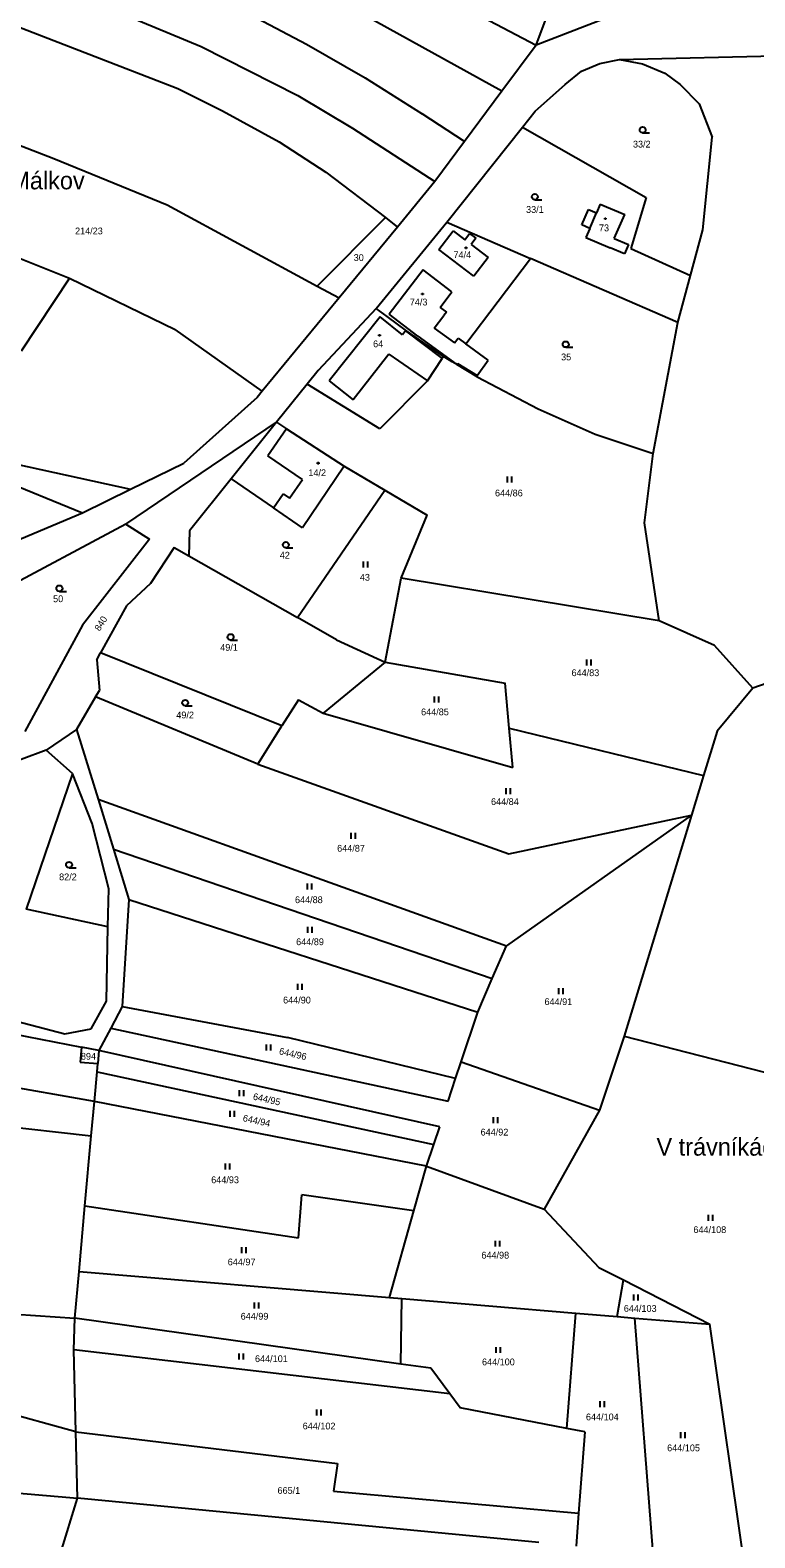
# Model space of a CAD drawing. Extents: x -791032 to -787751, y -1106872 to -1104403.
# Drawn here: x -789370.7 to -789189, y -1105599.2 to -1105221.6 of the extents above; entities that cross this region are included whole.
import ezdxf

# ---------------------------------------------------------------- set-up
doc = ezdxf.new("R2010")
doc.units = 0
for name, color, linetype in [('Vrstva 1', 7, 'Continuous'), ('Vrstva 14', 7, 'Continuous'), ('Vrstva 15', 7, 'Continuous'), ('Vrstva 2', 7, 'Continuous'), ('Vrstva 23', 7, 'Continuous'), ('Vrstva 25', 7, 'Continuous'), ('Vrstva 36', 7, 'Continuous'), ('Vrstva 39', 7, 'Continuous')]:
    doc.layers.add(name, color=color, linetype=linetype)

msp = doc.modelspace()

# ---------------------------------------------------------------- linework, layer by layer
at = {"layer": 'Vrstva 1'}
for p, q in [((-789285.39, -1105203.5), (-789243.84, -1105225.4)), ((-789370.26, -1105208.04), (-789327.75, -1105225.68)), ((-789252.41, -1105236.92), (-789298.86, -1105211.23)), ((-789243.84, -1105225.4), (-789238.63, -1105211.34)), ((-789386.31, -1105215.88), (-789333.63, -1105236.24)), ((-789313.74, -1105218.64), (-789301.43, -1105225.11)), ((-789226.96, -1105218.88), (-789243.84, -1105225.4)), ((-789301.43, -1105225.11), (-789286.69, -1105233.54)), ((-789327.75, -1105225.68), (-789303.58, -1105237.99)), ((-789243.84, -1105225.4), (-789252.41, -1105236.92)), ((-789227.84, -1105229.97), (-789222.94, -1105228.96)), ((-789222.94, -1105228.96), (-789175.36, -1105227.85)), ((-789222.94, -1105228.96), (-789217.17, -1105230.01)), ((-789236.59, -1105235.22), (-789232.43, -1105231.85)), ((-789232.43, -1105231.85), (-789227.84, -1105229.97)), ((-789217.17, -1105230.01), (-789211.57, -1105232.35)), ((-789211.57, -1105232.35), (-789207.7, -1105235.2)), ((-789333.63, -1105236.24), (-789322.44, -1105241.84)), ((-789286.69, -1105233.54), (-789272.38, -1105242.59)), ((-789240.29, -1105238.55), (-789236.59, -1105235.22)), ((-789207.7, -1105235.2), (-789202.93, -1105240.1)), ((-789303.58, -1105237.99), (-789289.9, -1105246.16)), ((-789252.41, -1105236.92), (-789261.75, -1105249.48)), ((-789244.09, -1105241.93), (-789240.29, -1105238.55)), ((-789202.93, -1105240.1), (-789199.71, -1105248.4)), ((-789322.44, -1105241.84), (-789308.28, -1105249.58)), ((-789261.75, -1105249.48), (-789272.38, -1105242.59)), ((-789247.25, -1105245.91), (-789244.09, -1105241.93)), ((-789388.44, -1105244.65), (-789364.69, -1105253.72)), ((-789289.9, -1105246.16), (-789269.22, -1105259.52)), ((-789266.18, -1105269.7), (-789247.25, -1105245.91)), ((-789247.25, -1105245.91), (-789216.22, -1105263.55)), ((-789308.28, -1105249.58), (-789296.51, -1105257.14)), ((-789261.75, -1105249.48), (-789269.22, -1105259.52)), ((-789202.09, -1105271.58), (-789199.71, -1105248.4)), ((-789364.69, -1105253.72), (-789336.29, -1105265.34)), ((-789296.51, -1105257.14), (-789281.6, -1105268.55)), ((-789269.22, -1105259.52), (-789278.59, -1105270.91)), ((-789336.29, -1105265.34), (-789298.72, -1105285.7)), ((-789232.37, -1105270.39), (-789230.72, -1105266.53)), ((-789230.72, -1105266.53), (-789228.7, -1105267.39)), ((-789227.75, -1105265.19), (-789228.7, -1105267.39)), ((-789227.75, -1105265.19), (-789221.64, -1105267.79)), ((-789216.22, -1105263.55), (-789220.12, -1105276.28)), ((-789298.72, -1105285.7), (-789281.6, -1105268.55)), ((-789283.9, -1105291.34), (-789266.18, -1105269.7)), ((-789281.6, -1105268.55), (-789278.59, -1105270.91)), ((-789266.18, -1105269.7), (-789245.27, -1105278.79)), ((-789230.35, -1105271.25), (-789232.37, -1105270.39)), ((-789224.26, -1105273.8), (-789221.64, -1105267.79)), ((-789278.59, -1105270.91), (-789293.22, -1105288.68)), ((-789268.2, -1105276.58), (-789264.6, -1105271.89)), ((-789264.6, -1105271.89), (-789261.74, -1105274.1)), ((-789261.74, -1105274.1), (-789260.51, -1105272.51)), ((-789260.51, -1105272.51), (-789258.92, -1105273.69)), ((-789258.92, -1105273.69), (-789260.15, -1105275.29)), ((-789230.35, -1105271.25), (-789231.34, -1105273.55)), ((-789231.34, -1105273.55), (-789225.26, -1105276.09)), ((-789224.26, -1105273.8), (-789220.7, -1105275.29)), ((-789205.18, -1105283.05), (-789202.09, -1105271.58)), ((-789382.55, -1105275), (-789360.79, -1105283.75)), ((-789259.48, -1105283.24), (-789268.2, -1105276.58)), ((-789260.15, -1105275.29), (-789255.88, -1105278.56)), ((-789221.66, -1105277.59), (-789225.26, -1105276.09)), ((-789220.7, -1105275.29), (-789221.66, -1105277.59)), ((-789220.12, -1105276.28), (-789205.18, -1105283.05)), ((-789261.47, -1105300.17), (-789245.27, -1105278.79)), ((-789255.88, -1105278.56), (-789259.48, -1105283.24)), ((-789208.35, -1105294.83), (-789245.27, -1105278.79)), ((-789360.79, -1105283.75), (-789372.88, -1105302)), ((-789360.79, -1105283.75), (-789334.28, -1105296.6)), ((-789298.72, -1105285.7), (-789293.22, -1105288.68)), ((-789208.35, -1105294.83), (-789205.18, -1105283.05)), ((-789293.22, -1105288.68), (-789312.46, -1105312.05)), ((-789283.9, -1105291.34), (-789298.48, -1105306.86)), ((-789281.14, -1105293.36), (-789283.9, -1105291.34)), ((-789312.46, -1105312.05), (-789334.28, -1105296.6)), ((-789276.3, -1105296.9), (-789281.14, -1105293.36)), ((-789267.05, -1105303.34), (-789276.3, -1105296.9)), ((-789214.52, -1105327.65), (-789208.35, -1105294.83)), ((-789255.84, -1105304.27), (-789261.47, -1105300.17)), ((-789271.03, -1105309.45), (-789267.36, -1105303.81)), ((-789267.05, -1105303.34), (-789267.36, -1105303.81)), ((-789264.87, -1105304.65), (-789267.05, -1105303.34)), ((-789258.6, -1105308.11), (-789255.84, -1105304.27)), ((-789298.48, -1105306.86), (-789301.19, -1105310.24)), ((-789263.73, -1105305.34), (-789264.87, -1105304.65)), ((-789263.58, -1105305.1), (-789263.73, -1105305.34)), ((-789258.63, -1105308.41), (-789263.73, -1105305.34)), ((-789263.58, -1105305.1), (-789258.6, -1105308.11)), ((-789312.46, -1105312.05), (-789313.76, -1105313.63)), ((-789301.19, -1105310.24), (-789308.87, -1105319.81)), ((-789283.02, -1105321.43), (-789301.19, -1105310.24)), ((-789271.03, -1105309.45), (-789283.02, -1105321.43)), ((-789258.63, -1105308.41), (-789243.3, -1105316.44)), ((-789313.76, -1105313.63), (-789332.15, -1105330.05)), ((-789243.3, -1105316.44), (-789229.02, -1105322.78)), ((-789346.71, -1105345.3), (-789308.87, -1105319.81)), ((-789308.87, -1105319.81), (-789320.23, -1105333.97)), ((-789308.87, -1105319.81), (-789306.41, -1105321.42)), ((-789306.41, -1105321.42), (-789291.98, -1105330.84)), ((-789229.02, -1105322.78), (-789214.52, -1105327.65)), ((-789395.29, -1105327.04), (-789357.53, -1105342.45)), ((-789377.52, -1105329.52), (-789345.54, -1105336.59)), ((-789345.54, -1105336.59), (-789332.15, -1105330.05)), ((-789291.98, -1105330.84), (-789302.36, -1105346.26)), ((-789291.98, -1105330.84), (-789281.77, -1105336.81)), ((-789216.65, -1105344.97), (-789214.52, -1105327.65)), ((-789320.23, -1105333.97), (-789330.68, -1105346.99)), ((-789320.23, -1105333.97), (-789309.63, -1105341.26)), ((-789357.53, -1105342.45), (-789345.54, -1105336.59)), ((-789303.67, -1105368.7), (-789281.77, -1105336.81)), ((-789281.77, -1105336.81), (-789271.14, -1105343.03)), ((-789302.36, -1105346.26), (-789309.63, -1105341.26)), ((-789409.67, -1105364.4), (-789357.53, -1105342.45)), ((-789346.71, -1105345.3), (-789381.96, -1105364.16)), ((-789346.71, -1105345.3), (-789340.72, -1105349.12)), ((-789277.68, -1105358.85), (-789271.14, -1105343.03)), ((-789213.03, -1105369.56), (-789216.65, -1105344.97)), ((-789340.72, -1105349.12), (-789357.5, -1105370.6)), ((-789330.68, -1105346.99), (-789330.92, -1105353.22)), ((-789334.57, -1105351.15), (-789340.51, -1105360.15)), ((-789334.57, -1105351.15), (-789330.92, -1105353.22)), ((-789330.92, -1105353.22), (-789303.67, -1105368.7)), ((-789340.51, -1105360.15), (-789346.51, -1105365.76)), ((-789281.67, -1105379.86), (-789277.68, -1105358.85)), ((-789213.03, -1105369.56), (-789277.68, -1105358.85)), ((-789346.51, -1105365.76), (-789352.99, -1105377.52)), ((-789293.88, -1105374.26), (-789303.67, -1105368.7)), ((-789357.5, -1105370.6), (-789371.98, -1105397.25)), ((-789199.13, -1105375.67), (-789213.03, -1105369.56)), ((-789293.88, -1105374.26), (-789281.67, -1105379.86)), ((-789189.55, -1105386.43), (-789199.13, -1105375.67)), ((-789353.96, -1105379.28), (-789352.99, -1105377.52)), ((-789353.96, -1105379.28), (-789353.31, -1105386.97)), ((-789307.55, -1105395.84), (-789352.99, -1105377.52)), ((-789281.67, -1105379.86), (-789297.25, -1105392.63)), ((-789281.67, -1105379.86), (-789251.59, -1105385.16)), ((-789177.3, -1105382.12), (-789189.55, -1105386.43)), ((-789354.27, -1105388.6), (-789353.31, -1105386.97)), ((-789250.58, -1105396.4), (-789251.59, -1105385.16)), ((-789189.55, -1105386.43), (-789198.49, -1105397.16)), ((-789354.27, -1105388.6), (-789359, -1105396.72)), ((-789313.59, -1105405.39), (-789354.27, -1105388.6)), ((-789303.42, -1105389.34), (-789307.55, -1105395.84)), ((-789303.42, -1105389.34), (-789297.25, -1105392.63)), ((-789297.25, -1105392.63), (-789249.7, -1105406.22)), ((-789359, -1105396.72), (-789366.67, -1105401.92)), ((-789359, -1105396.72), (-789353.64, -1105414.19)), ((-789313.59, -1105405.39), (-789307.55, -1105395.84)), ((-789250.58, -1105396.4), (-789201.88, -1105408.26)), ((-789249.7, -1105406.22), (-789250.58, -1105396.4)), ((-789198.49, -1105397.16), (-789201.88, -1105408.26)), ((-789366.67, -1105401.92), (-789394.2, -1105412.1)), ((-789360.03, -1105407.78), (-789366.67, -1105401.92)), ((-789313.59, -1105405.39), (-789250.65, -1105427.9)), ((-789360.03, -1105407.78), (-789371.65, -1105441.77)), ((-789355.07, -1105420.31), (-789360.03, -1105407.78)), ((-789201.88, -1105408.26), (-789204.91, -1105418.19)), ((-789353.64, -1105414.19), (-789349.8, -1105426.7)), ((-789353.64, -1105414.19), (-789251.26, -1105450.9)), ((-789350.96, -1105436.62), (-789355.07, -1105420.31)), ((-789204.91, -1105418.19), (-789251.26, -1105450.9)), ((-789250.65, -1105427.9), (-789204.91, -1105418.19)), ((-789204.91, -1105418.19), (-789221.79, -1105473.54)), ((-789349.8, -1105426.7), (-789345.92, -1105439.33)), ((-789349.8, -1105426.7), (-789254.83, -1105459.12)), ((-789351.15, -1105446.16), (-789350.96, -1105436.62)), ((-789345.92, -1105439.33), (-789347.58, -1105466.12)), ((-789345.92, -1105439.33), (-789258.47, -1105467.51)), ((-789351.15, -1105446.16), (-789371.65, -1105441.77)), ((-789351.53, -1105464.8), (-789351.15, -1105446.16)), ((-789254.83, -1105459.12), (-789251.26, -1105450.9)), ((-789258.47, -1105467.51), (-789254.83, -1105459.12)), ((-789411.01, -1105460.08), (-789361.97, -1105472.94)), ((-789355.35, -1105471.72), (-789351.53, -1105464.8)), ((-789347.58, -1105466.12), (-789350.45, -1105471.55)), ((-789347.58, -1105466.12), (-789306.15, -1105473.87)), ((-789262.61, -1105479.95), (-789258.47, -1105467.51)), ((-789378.46, -1105472.29), (-789357.82, -1105476.28)), ((-789361.97, -1105472.94), (-789355.35, -1105471.72)), ((-789350.45, -1105471.55), (-789353.41, -1105477.13)), ((-789350.45, -1105471.55), (-789265.9, -1105489.85)), ((-789264.01, -1105484.16), (-789306.15, -1105473.87)), ((-789221.79, -1105473.54), (-789227.97, -1105492.04)), ((-789221.79, -1105473.54), (-789163.41, -1105488.56)), ((-789357.82, -1105476.28), (-789358.13, -1105480.02)), ((-789353.41, -1105477.13), (-789357.82, -1105476.28)), ((-789353.41, -1105477.13), (-789353.7, -1105480.42)), ((-789268.01, -1105496.22), (-789353.41, -1105477.13)), ((-789354.56, -1105489.92), (-789416.33, -1105479.05)), ((-789358.13, -1105480.02), (-789353.7, -1105480.42)), ((-789353.88, -1105482.44), (-789353.7, -1105480.42)), ((-789264.01, -1105484.16), (-789262.61, -1105479.95)), ((-789262.61, -1105479.95), (-789227.97, -1105492.04)), ((-789354.56, -1105489.92), (-789353.88, -1105482.44)), ((-789353.88, -1105482.44), (-789269.48, -1105500.65)), ((-789265.9, -1105489.85), (-789264.01, -1105484.16)), ((-789405.54, -1105492.93), (-789355.33, -1105498.49)), ((-789355.33, -1105498.49), (-789354.56, -1105489.92)), ((-789271.3, -1105506.12), (-789354.56, -1105489.92)), ((-789227.97, -1105492.04), (-789241.81, -1105516.87)), ((-789269.48, -1105500.65), (-789268.01, -1105496.22)), ((-789356.91, -1105516.06), (-789355.33, -1105498.49)), ((-789271.3, -1105506.12), (-789269.48, -1105500.65)), ((-789274.46, -1105517.27), (-789271.3, -1105506.12)), ((-789271.3, -1105506.12), (-789241.81, -1105516.87)), ((-789358.39, -1105532.44), (-789356.91, -1105516.06)), ((-789356.91, -1105516.06), (-789303.41, -1105524.01)), ((-789303.41, -1105524.01), (-789302.59, -1105513.26)), ((-789274.46, -1105517.27), (-789302.59, -1105513.26)), ((-789280.59, -1105538.96), (-789274.46, -1105517.27)), ((-789241.81, -1105516.87), (-789228.12, -1105531.44)), ((-789359.45, -1105544.16), (-789358.39, -1105532.44)), ((-789358.39, -1105532.44), (-789280.59, -1105538.96)), ((-789228.12, -1105531.44), (-789221.97, -1105534.59)), ((-789223.56, -1105543.75), (-789221.97, -1105534.59)), ((-789221.97, -1105534.59), (-789200.28, -1105545.7)), ((-789400.71, -1105541.35), (-789359.45, -1105544.16)), ((-789280.59, -1105538.96), (-789277.5, -1105539.22)), ((-789277.73, -1105555.64), (-789277.5, -1105539.22)), ((-789277.5, -1105539.22), (-789233.9, -1105542.88)), ((-789359.67, -1105552.06), (-789359.45, -1105544.16)), ((-789277.73, -1105555.64), (-789359.45, -1105544.16)), ((-789236.16, -1105571.75), (-789233.9, -1105542.88)), ((-789233.9, -1105542.88), (-789223.56, -1105543.75)), ((-789223.56, -1105543.75), (-789219.1, -1105544.12)), ((-789214.49, -1105603.07), (-789219.1, -1105544.12)), ((-789219.1, -1105544.12), (-789200.28, -1105545.7)), ((-789190.03, -1105617.13), (-789200.28, -1105545.7)), ((-789359.17, -1105572.6), (-789359.67, -1105552.06)), ((-789265.44, -1105563.13), (-789359.67, -1105552.06)), ((-789270.26, -1105556.69), (-789277.73, -1105555.64)), ((-789265.44, -1105563.13), (-789270.26, -1105556.69)), ((-789359.17, -1105572.6), (-789405.78, -1105559.76)), ((-789262.84, -1105566.61), (-789265.44, -1105563.13)), ((-789236.16, -1105571.75), (-789262.84, -1105566.61)), ((-789358.76, -1105589.25), (-789359.17, -1105572.6)), ((-789359.17, -1105572.6), (-789293.6, -1105580.53)), ((-789231.61, -1105572.62), (-789236.16, -1105571.75)), ((-789231.61, -1105572.62), (-789233.18, -1105593.02)), ((-789293.6, -1105580.53), (-789294.6, -1105587.44)), ((-789384.93, -1105586.95), (-789358.76, -1105589.25)), ((-789294.6, -1105587.44), (-789233.18, -1105593.02)), ((-789363.03, -1105603.06), (-789358.76, -1105589.25)), ((-789243.14, -1105600.32), (-789358.76, -1105589.25)), ((-789233.18, -1105593.02), (-789233.81, -1105601.22))]:
    msp.add_line(p, q, dxfattribs=at)
at = {"layer": 'Vrstva 2'}
for p, q in [((-789230.35, -1105271.25), (-789228.7, -1105267.39)), ((-789272.13, -1105281.61), (-789280.65, -1105292.72)), ((-789264.93, -1105287.13), (-789272.13, -1105281.61)), ((-789267.92, -1105291.03), (-789264.93, -1105287.13)), ((-789273.45, -1105298.24), (-789280.65, -1105292.72)), ((-789269.39, -1105296.23), (-789266.99, -1105293.11)), ((-789267.92, -1105291.03), (-789266.32, -1105292.2)), ((-789266.32, -1105292.2), (-789266.99, -1105293.11)), ((-789282.95, -1105293.42), (-789295.69, -1105309.44)), ((-789277.34, -1105297.88), (-789282.95, -1105293.42)), ((-789276.56, -1105296.9), (-789277.34, -1105297.88)), ((-789276.56, -1105296.9), (-789267.36, -1105303.81)), ((-789269.39, -1105296.23), (-789264.26, -1105299.93)), ((-789273.45, -1105298.24), (-789263.73, -1105305.34)), ((-789264.26, -1105299.93), (-789263.39, -1105298.77)), ((-789263.39, -1105298.77), (-789261.47, -1105300.17)), ((-789280.72, -1105302.74), (-789289.66, -1105314.16)), ((-789280.72, -1105302.74), (-789271.03, -1105309.45)), ((-789295.69, -1105309.44), (-789289.66, -1105314.16)), ((-789306.41, -1105321.42), (-789311.07, -1105328.2)), ((-789302.4, -1105334.16), (-789311.07, -1105328.2)), ((-789305.61, -1105338.84), (-789302.4, -1105334.16)), ((-789309.63, -1105341.26), (-789307.21, -1105337.74)), ((-789307.21, -1105337.74), (-789305.61, -1105338.84))]:
    msp.add_line(p, q, dxfattribs=at)
at = {"layer": 'Vrstva 23'}
for p, q in [((-789217.13, -1105247.33), (-789215.38, -1105247.33)), ((-789244.15, -1105264.1), (-789242.4, -1105264.1)), ((-789236.41, -1105301.04), (-789234.66, -1105301.04)), ((-789251.01, -1105334.87), (-789251.01, -1105333.37)), ((-789250.01, -1105333.37), (-789250.01, -1105334.87)), ((-789306.56, -1105351.25), (-789304.81, -1105351.25)), ((-789287.12, -1105356.21), (-789287.12, -1105354.71)), ((-789286.12, -1105354.71), (-789286.12, -1105356.21)), ((-789363.32, -1105362.16), (-789361.57, -1105362.16)), ((-789320.41, -1105374.34), (-789318.66, -1105374.34)), ((-789231.14, -1105380.68), (-789231.14, -1105379.18)), ((-789230.14, -1105379.18), (-789230.14, -1105380.68)), ((-789331.8, -1105390.8), (-789330.05, -1105390.8)), ((-789269.33, -1105389.98), (-789269.33, -1105388.48)), ((-789268.33, -1105388.48), (-789268.33, -1105389.98)), ((-789251.34, -1105412.96), (-789251.34, -1105411.46)), ((-789250.34, -1105411.46), (-789250.34, -1105412.96)), ((-789290.19, -1105424.12), (-789290.19, -1105422.62)), ((-789289.19, -1105422.62), (-789289.19, -1105424.12)), ((-789360.91, -1105431.37), (-789359.16, -1105431.37)), ((-789301.15, -1105436.84), (-789301.15, -1105435.34)), ((-789300.15, -1105435.34), (-789300.15, -1105436.84)), ((-789301.03, -1105447.7), (-789301.03, -1105446.2)), ((-789300.03, -1105446.2), (-789300.03, -1105447.7)), ((-789303.6, -1105461.96), (-789303.6, -1105460.46)), ((-789302.6, -1105460.46), (-789302.6, -1105461.96)), ((-789238.14, -1105463.05), (-789238.14, -1105461.55)), ((-789237.14, -1105461.55), (-789237.14, -1105463.05)), ((-789311.39, -1105477.15), (-789311.39, -1105475.65)), ((-789310.39, -1105475.65), (-789310.39, -1105477.15)), ((-789318.15, -1105488.55), (-789318.15, -1105487.05)), ((-789317.15, -1105487.05), (-789317.15, -1105488.55)), ((-789320.55, -1105493.74), (-789320.55, -1105492.24)), ((-789319.55, -1105492.24), (-789319.55, -1105493.74)), ((-789254.5, -1105495.29), (-789254.5, -1105493.79)), ((-789253.5, -1105493.79), (-789253.5, -1105495.29)), ((-789321.71, -1105506.95), (-789321.71, -1105505.45)), ((-789320.71, -1105505.45), (-789320.71, -1105506.95)), ((-789200.63, -1105519.79), (-789200.63, -1105518.29)), ((-789199.63, -1105518.29), (-789199.63, -1105519.79)), ((-789317.63, -1105527.86), (-789317.63, -1105526.36)), ((-789316.63, -1105526.36), (-789316.63, -1105527.86)), ((-789254.01, -1105526.25), (-789254.01, -1105524.75)), ((-789253.01, -1105524.75), (-789253.01, -1105526.25)), ((-789219.36, -1105539.7), (-789219.36, -1105538.2)), ((-789218.36, -1105538.2), (-789218.36, -1105539.7)), ((-789314.42, -1105541.74), (-789314.42, -1105540.24)), ((-789313.42, -1105540.24), (-789313.42, -1105541.74)), ((-789318.29, -1105554.51), (-789318.29, -1105553.01)), ((-789317.29, -1105553.01), (-789317.29, -1105554.51)), ((-789253.82, -1105552.88), (-789253.82, -1105551.38)), ((-789252.82, -1105551.38), (-789252.82, -1105552.88)), ((-789227.78, -1105566.48), (-789227.78, -1105564.98)), ((-789226.78, -1105564.98), (-789226.78, -1105566.48)), ((-789298.77, -1105568.56), (-789298.77, -1105567.06)), ((-789297.77, -1105567.06), (-789297.77, -1105568.56)), ((-789207.57, -1105574.22), (-789207.57, -1105572.72)), ((-789206.57, -1105572.72), (-789206.57, -1105574.22))]:
    msp.add_line(p, q, dxfattribs=at)
for centre in [(-789217.13, -1105246.58), (-789244.15, -1105263.35), (-789236.41, -1105300.29), (-789306.56, -1105350.5), (-789363.32, -1105361.41), (-789320.41, -1105373.59), (-789331.8, -1105390.05), (-789360.91, -1105430.62)]:
    msp.add_circle(centre, 0.75, dxfattribs=at)
at = {"layer": 'Vrstva 25'}
for p, q in [((-789226.64, -1105268.68), (-789226.34, -1105268.68)), ((-789226.64, -1105268.98), (-789226.64, -1105268.68)), ((-789226.34, -1105268.98), (-789226.64, -1105268.98)), ((-789226.34, -1105268.68), (-789226.34, -1105268.98)), ((-789261.55, -1105275.97), (-789261.25, -1105275.97)), ((-789261.55, -1105276.27), (-789261.55, -1105275.97)), ((-789261.25, -1105276.27), (-789261.55, -1105276.27)), ((-789261.25, -1105275.97), (-789261.25, -1105276.27)), ((-789272.48, -1105287.52), (-789272.18, -1105287.52)), ((-789272.48, -1105287.82), (-789272.48, -1105287.52)), ((-789272.18, -1105287.82), (-789272.48, -1105287.82)), ((-789272.18, -1105287.52), (-789272.18, -1105287.82)), ((-789283.25, -1105297.87), (-789282.95, -1105297.87)), ((-789283.25, -1105298.17), (-789283.25, -1105297.87)), ((-789282.95, -1105298.17), (-789283.25, -1105298.17)), ((-789282.95, -1105297.87), (-789282.95, -1105298.17)), ((-789298.6, -1105329.91), (-789298.3, -1105329.91)), ((-789298.6, -1105330.21), (-789298.6, -1105329.91)), ((-789298.3, -1105330.21), (-789298.6, -1105330.21)), ((-789298.3, -1105329.91), (-789298.3, -1105330.21))]:
    msp.add_line(p, q, dxfattribs=at)

# ---------------------------------------------------------------- texts
at = {"layer": 'Vrstva 14'}
for s, p in [('33/2', (-789219.56, -1105251.01)), ('33/1', (-789246.353, -1105267.37)), ('214/23', (-789359.399, -1105272.75)), ('30', (-789289.556, -1105279.41)), ('35', (-789237.573, -1105304.3)), ('644/86', (-789254.141, -1105338.38)), ('42', (-789308.092, -1105353.95)), ('43', (-789288.023, -1105359.48)), ('50', (-789364.902, -1105364.86)), ('49/1', (-789323.009, -1105377.04)), ('644/83', (-789234.961, -1105383.38)), ('644/85', (-789272.668, -1105393.19)), ('49/2', (-789334.026, -1105393.96)), ('644/84', (-789255.137, -1105415.66)), ('644/87', (-789293.708, -1105427.34)), ('82/2', (-789363.399, -1105434.51)), ('644/88', (-789304.271, -1105440.23)), ('644/89', (-789303.981, -1105450.75)), ('644/90', (-789307.261, -1105465.35)), ('644/91', (-789241.735, -1105465.75)), ('894', (-789357.942, -1105479.43)), ('644/92', (-789257.751, -1105498.42)), ('644/93', (-789325.272, -1105510.36)), ('644/108', (-789204.404, -1105522.85)), ('644/97', (-789321.128, -1105530.93)), ('644/98', (-789257.551, -1105529.23)), ('644/103', (-789221.854, -1105542.58)), ('644/99', (-789317.892, -1105544.53)), ('644/101', (-789314.297, -1105555.16)), ('644/100', (-789257.403, -1105555.96)), ('644/104', (-789231.35, -1105569.74)), ('644/102', (-789302.344, -1105572.02)), ('644/105', (-789210.99, -1105577.49)), ('665/1', (-789308.65, -1105588.16))]:
    msp.add_text(s, height=1.7, dxfattribs=at).set_placement(p)
for s, rotation, p in [('840', 57.95046, (-789353.227, -1105372.249)), ('644/96', 347.51754, (-789308.371, -1105478.053)), ('644/95', 347.24043, (-789314.923, -1105489.399)), ('644/94', 347.82858, (-789317.463, -1105494.81))]:
    msp.add_text(s, height=1.7, rotation=rotation, dxfattribs=at).set_placement(p)
at = {"layer": 'Vrstva 15'}
for s, p in [('73', (-789228.083, -1105271.98)), ('74/4', (-789264.548, -1105278.71)), ('74/3', (-789275.502, -1105290.55)), ('64', (-789284.693, -1105301.02)), ('14/2', (-789300.919, -1105333.3))]:
    msp.add_text(s, height=1.7, dxfattribs=at).set_placement(p)
at = {"layer": 'Vrstva 36'}
msp.add_text('Drahenický Málkov', height=4.4, dxfattribs=at).set_placement((-789406.69, -1105261.47))
at = {"layer": 'Vrstva 39'}
msp.add_text('V trávníkách', height=4.4, dxfattribs=at).set_placement((-789213.66, -1105503.46))

doc.saveas('drawing.dxf')
